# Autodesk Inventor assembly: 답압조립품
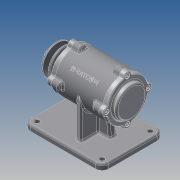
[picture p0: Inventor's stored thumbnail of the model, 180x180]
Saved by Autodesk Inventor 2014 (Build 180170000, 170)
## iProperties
Created: 2015-12
Part Number: 답압조립품
Document SubType Name: Assembly
Designer: user
Author: user
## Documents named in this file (11)
- C:\Users\user\Desktop\공택수\답압조립품.iam
- C:\Users\user\Desktop\공택수\본체.ipt
- C:\Users\user\Desktop\공택수\V-벨트풀리.ipt
- C:\Users\user\Desktop\공택수\너트 M12x1.25.ipt
- C:\Users\user\Desktop\공택수\베어링 6204.ipt
- C:\Users\user\Desktop\공택수\볼트 M4 x 12.ipt
- C:\Users\user\Desktop\공택수\오일실.ipt
- C:\Users\user\Desktop\공택수\축.ipt
- C:\Users\user\Desktop\공택수\커버.ipt
- C:\Users\user\Desktop\공택수\커버2.ipt
- C:\Users\user\Desktop\공택수\키(4 x 4 x 12).ipt
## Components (6 placed, 5 different names)
1. V-벨트풀리:1 — Mate:12, Mate:13, Mate:14, Mate:16
2. KS B 1012 클래스 1 일반 - 미터 M12x1.25:1 — Mate:15, Mate:16, Angle:1
3. KS B 2023 6204 - 20 x 47 x 14:1 — Mate:6, Mate:7, Mate:17
4. KS B 2804 D D - 20 32 8:1 — Mate:2, Mate:3
5. KS B 1311 (I) 4 x 4 x 12:1 — Mate:9, Mate:10, Mate:11, Mate:13, Angle:1
6. KS B 2023 6204 - 20 x 47 x 14:2 — Mate:4, Mate:5, Mate:18
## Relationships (17: Mate 16, Angle 1)
- Mate:2: KS B 2804 D D - 20 32 8:1
- Mate:3: KS B 2804 D D - 20 32 8:1
- Mate:4: KS B 2023 6204 - 20 x 47 x 14:2
- Mate:5: KS B 2023 6204 - 20 x 47 x 14:2
- Mate:6: KS B 2023 6204 - 20 x 47 x 14:1
- Mate:7: KS B 2023 6204 - 20 x 47 x 14:1
- Mate:9: KS B 1311 (I) 4 x 4 x 12:1
- Mate:10: KS B 1311 (I) 4 x 4 x 12:1
- Mate:11: KS B 1311 (I) 4 x 4 x 12:1
- Mate:12: V-벨트풀리:1
- Mate:13: V-벨트풀리:1 ↔ KS B 1311 (I) 4 x 4 x 12:1
- Mate:14: V-벨트풀리:1
- Mate:15: KS B 1012 클래스 1 일반 - 미터 M12x1.25:1
- Mate:16: V-벨트풀리:1 ↔ KS B 1012 클래스 1 일반 - 미터 M12x1.25:1
- Mate:17: KS B 2023 6204 - 20 x 47 x 14:1
- Mate:18: KS B 2023 6204 - 20 x 47 x 14:2
- Angle:1: KS B 1012 클래스 1 일반 - 미터 M12x1.25:1 ↔ KS B 1311 (I) 4 x 4 x 12:1
